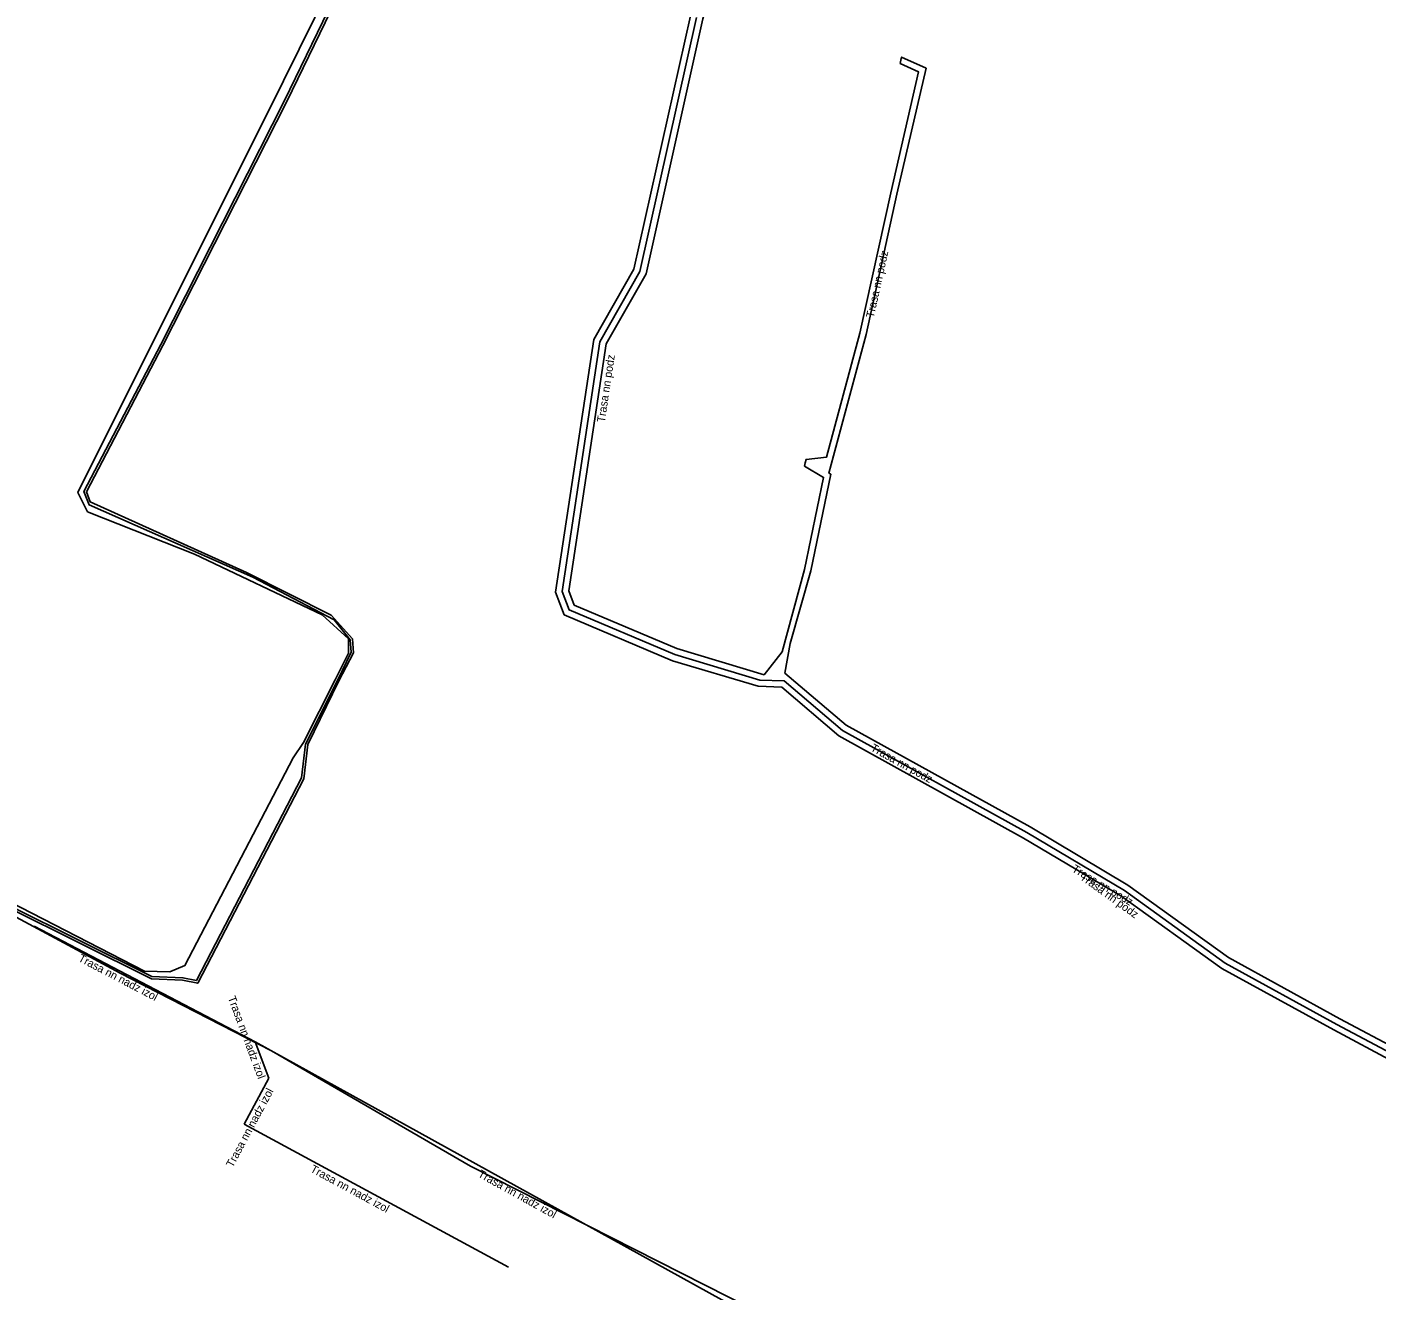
# Model space of a CAD drawing. Extents: x -528089 to -527692, y -1079306 to -1078676.
# Drawn here: x -528006 to -527921.7, y -1079016.7 to -1078937.8 of the extents above; entities that cross this region are included whole.
import ezdxf

# ---------------------------------------------------------------- set-up
doc = ezdxf.new("R2010")
doc.units = 0
for name, color, linetype in [('Popiskový text - Ostatní atributy Trasy', 7, 'Continuous'), ('Spojnice NN', 7, 'Continuous'), ('Spojnice VN', 7, 'Continuous')]:
    doc.layers.add(name, color=color, linetype=linetype)

msp = doc.modelspace()

# ---------------------------------------------------------------- linework, layer by layer
at = {"layer": 'Spojnice NN'}
for points in [[(-527950.354, -1078896.828), (-527953.033, -1078892.769), (-527953.865, -1078893.434), (-527955.71, -1078892.04), (-527962.44, -1078888.52), (-527963.051, -1078888.256), (-527963.713, -1078888.376), (-527974.175, -1078910.594), (-527982.325, -1078926.824), (-527989.864, -1078942.373), (-527997.603, -1078957.621), (-528002.414, -1078966.82), (-528002.07, -1078967.65), (-527991.84, -1078972.17), (-527986.771, -1078974.84)], [(-527950.354, -1078896.828), (-527952.922, -1078892.893), (-527953.84, -1078893.57), (-527955.74, -1078892.15), (-527962.51, -1078888.58), (-527963.06, -1078888.41), (-527963.61, -1078888.51), (-527974.04, -1078910.66), (-527982.19, -1078926.89), (-527989.73, -1078942.44), (-527997.47, -1078957.69), (-528002.25, -1078966.83), (-528002.01, -1078967.46), (-527992.25, -1078971.87), (-527986.953, -1078974.549)], [(-527959.45, -1078918.798), (-527960.218, -1078923.662), (-527963.731, -1078937.283), (-527967.282, -1078953.205), (-527969.775, -1078957.593), (-527972.108, -1078973.015), (-527971.767, -1078973.909), (-527965.354, -1078976.633), (-527959.902, -1078978.262), (-527958.774, -1078976.836), (-527957.385, -1078971.683), (-527956.185, -1078965.938), (-527957.378, -1078965.225), (-527957.33, -1078965.02)], [(-527964.509, -1078937.096), (-527968.037, -1078952.914), (-527970.544, -1078957.327), (-527972.931, -1078973.104), (-527972.393, -1078974.512), (-527965.626, -1078977.387), (-527960.285, -1078978.983), (-527958.803, -1078979.045), (-527955.238, -1078982.08), (-527943.689, -1078988.467), (-527937.609, -1078992.085), (-527931.314, -1078996.619), (-527924.32, -1079000.462), (-527920.587, -1079002.444)], [(-527920.4, -1079002.09), (-527924.13, -1079000.11), (-527931.1, -1078996.28), (-527937.39, -1078991.75), (-527943.49, -1078988.12), (-527955.01, -1078981.75), (-527958.65, -1078978.65), (-527960.17, -1078978.6), (-527965.49, -1078977.01), (-527972.08, -1078974.21), (-527972.52, -1078973.06), (-527970.16, -1078957.46), (-527967.66, -1078953.06), (-527964.12, -1078937.19)], [(-527951.407, -1078940.069), (-527951.36, -1078939.87), (-527951.313, -1078939.671), (-527949.788, -1078940.366), (-527951.605, -1078948.234), (-527953.536, -1078957.007), (-527955.859, -1078965.668), (-527955.735, -1078965.742), (-527956.995, -1078971.777), (-527958.27, -1078976.31), (-527958.608, -1078978.16), (-527954.781, -1078981.419), (-527943.291, -1078987.773), (-527937.17, -1078991.415), (-527930.886, -1078995.941), (-527923.94, -1078999.758), (-527920.173, -1079001.758), (-527918.304, -1078999.016), (-527916.724, -1078992.662), (-527915.621, -1078988.219), (-527916.874, -1078986.911)], [(-527957.33, -1078965.02), (-527957.281, -1078964.813), (-527956.008, -1078964.676), (-527953.924, -1078956.913), (-527951.995, -1078948.146), (-527950.252, -1078940.594), (-527951.407, -1078940.069)], [(-527986.953, -1078974.549), (-527985.63, -1078976.03), (-527985.55, -1078976.89), (-527986.47, -1078978.65), (-527988.42, -1078982.62), (-527988.66, -1078984.76), (-527995.29, -1078997.54), (-527996.24, -1078997.35), (-527998.19, -1078997.27), (-528011.6, -1078990.61)], [(-527986.771, -1078974.84), (-527985.775, -1078976.093), (-527985.703, -1078976.86), (-527986.56, -1078978.62), (-527988.55, -1078982.6), (-527988.806, -1078984.716), (-527995.371, -1078997.371), (-527996.222, -1078997.201), (-527998.152, -1078997.121), (-528011.565, -1078990.46)], [(-528005.509, -1078993.984), (-527991.703, -1079001.194)], [(-527991.703, -1079001.194), (-527990.852, -1079003.474)], [(-527991.703, -1079001.194), (-527955.651, -1079021.133)], [(-527990.852, -1079003.474), (-527992.382, -1079006.35)], [(-527992.382, -1079006.35), (-527975.883, -1079015.282)]]:
    msp.add_lwpolyline(points, dxfattribs=at)
at = {"layer": 'Spojnice VN'}
for points in [[(-527987.518, -1078974.53), (-527987.52, -1078974.529), (-527995.49, -1078970.73), (-528002.17, -1078968.08), (-528002.78, -1078966.87), (-527989.93, -1078941.16), (-527981.15, -1078923.37), (-527974.13, -1078909.71), (-527964.35, -1078889.11), (-527963.6, -1078888.1), (-527962.96, -1078887.99), (-527962.4, -1078888.34), (-527955.58, -1078891.9), (-527953.929, -1078893.274), (-527950.354, -1078896.828)], [(-527987.518, -1078974.53), (-527987.52, -1078974.529), (-527995.49, -1078970.73), (-528002.17, -1078968.08), (-528002.78, -1078966.87), (-527989.93, -1078941.16), (-527981.15, -1078923.37), (-527974.13, -1078909.71), (-527964.35, -1078889.11), (-527963.6, -1078888.1), (-527962.96, -1078887.99), (-527962.4, -1078888.34), (-527955.58, -1078891.9), (-527953.929, -1078893.274), (-527950.354, -1078896.828)], [(-528011.29, -1078990.26), (-527998.62, -1078996.79), (-527997.03, -1078996.83), (-527996.09, -1078996.44), (-527989.33, -1078983.45), (-527988.68, -1078982.5), (-527986.7, -1078978.59), (-527985.87, -1078976.92), (-527985.88, -1078976.03), (-527987.518, -1078974.53)], [(-528011.29, -1078990.26), (-527998.62, -1078996.79), (-527997.03, -1078996.83), (-527996.09, -1078996.44), (-527989.33, -1078983.45), (-527988.68, -1078982.5), (-527986.7, -1078978.59), (-527985.87, -1078976.92), (-527985.88, -1078976.03), (-527987.518, -1078974.53)], [(-527900.67, -1079080.75), (-527902.31, -1079079.5), (-527906.63, -1079073.48), (-527905.99, -1079070.78), (-527898.71, -1079055.64), (-527897.08, -1079052.2), (-527897.4, -1079050.06), (-527898.22, -1079048.86), (-527902.3, -1079046.36), (-527913.68, -1079040.68), (-527917.97, -1079040.28), (-527925.59, -1079036.9), (-527939.41, -1079029.3), (-527955.66, -1079020.73), (-527960.68, -1079017.89), (-527978.24, -1079008.97), (-527990.68, -1079001.77), (-528000.14, -1078996.92), (-528007.17, -1078993.13)], [(-527900.67, -1079080.75), (-527902.31, -1079079.5), (-527906.63, -1079073.48), (-527905.99, -1079070.78), (-527898.71, -1079055.64), (-527897.08, -1079052.2), (-527897.4, -1079050.06), (-527898.22, -1079048.86), (-527902.3, -1079046.36), (-527913.68, -1079040.68), (-527917.97, -1079040.28), (-527925.59, -1079036.9), (-527939.41, -1079029.3), (-527955.66, -1079020.73), (-527960.68, -1079017.89), (-527978.24, -1079008.97), (-527990.68, -1079001.77), (-528000.14, -1078996.92), (-528007.17, -1078993.13)]]:
    msp.add_lwpolyline(points, dxfattribs=at)

# ---------------------------------------------------------------- texts
at = {"layer": 'Popiskový text - Ostatní atributy Trasy'}
for s, rotation, p in [('Trasa nn podz', 77.59096, (-527953.056, -1078955.993)), ('Trasa nn podz', 81.39767, (-527969.864, -1078962.526)), ('Trasa nn podz', 331.05729, (-527953.296, -1078982.983)), ('Trasa nn podz', 329.24389, (-527940.716, -1078990.527)), ('Trasa nn podz', 324.23652, (-527940.207, -1078991.014)), ('Trasa nn nadz izol', 332.42478, (-528002.798, -1078996.134)), ('Trasa nn nadz izol', 290.45338, (-527993.42, -1078998.448)), ('Trasa nn nadz izol', 61.99347, (-527993.105, -1079009.093)), ('Trasa nn nadz izol', 331.57002, (-527988.302, -1079009.298)), ('Trasa nn nadz izol', 331.0552, (-527977.833, -1079009.608))]:
    msp.add_text(s, height=0.5, rotation=rotation, dxfattribs=at).set_placement(p)

doc.saveas('drawing.dxf')
